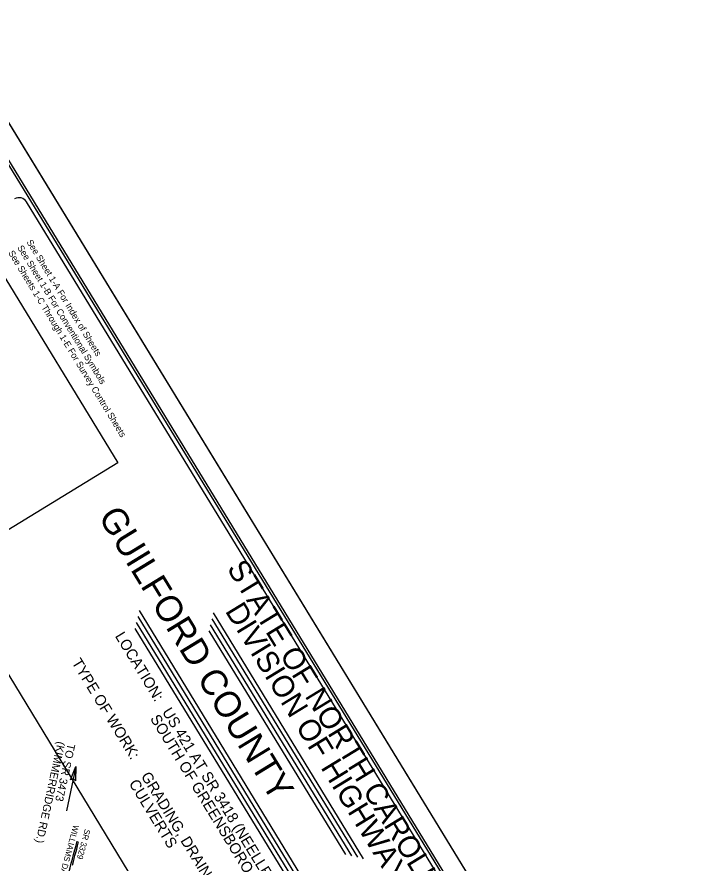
# Model space of a CAD drawing. Extents: x 1750583 to 1791140, y 783580 to 827376.
# Drawn here: x 1782418 to 1791140, y 815720 to 826460 of the extents above; entities that cross this region are included whole.
import ezdxf

# ---------------------------------------------------------------- set-up
doc = ezdxf.new("R2010")
doc.units = 0
for name, color, linetype in [('COGO Default Parcel', 7, 'Continuous'), ('Exist CMT EOP', 7, 'Continuous'), ('Prop Dimension Text', 7, 'Continuous'), ('Prop Terminator CELL', 7, 'Continuous'), ('Sheet Clip Boundary CELL', 7, 'Continuous'), ('Sheet Cutting Line CELL', 7, 'Continuous'), ('Sheet Data Field CELL', 7, 'Continuous'), ('Sheet Plot Border Inside CELL', 7, 'Continuous'), ('Sheet Plot Border Outside CELL', 7, 'Continuous'), ('Sheet Title CELL', 7, 'Continuous'), ('Sheet Title Data Points CELL', 7, 'Continuous')]:
    doc.layers.add(name, color=color, linetype=linetype)

msp = doc.modelspace()

# ---------------------------------------------------------------- linework, layer by layer
at = {"layer": 'COGO Default Parcel'}
msp.add_line((1783166, 816945), (1783048, 816382), dxfattribs=at)
at = {"layer": 'Exist CMT EOP'}
for points in [[(1782983, 815250), (1782998, 815306), (1783015, 815368), (1783030, 815426), (1783045, 815481), (1783062, 815545), (1783077, 815602), (1783093, 815661), (1783108, 815718), (1783116, 815746), (1783122, 815770), (1783138, 815829), (1783153, 815887), (1783168, 815943), (1783183, 815999)], [(1783123, 815695), (1783135, 815739), (1783144, 815774), (1783151, 815798), (1783155, 815816), (1783162, 815841), (1783169, 815866), (1783177, 815898), (1783188, 815939), (1783201, 815991)]]:
    msp.add_lwpolyline(points, dxfattribs=at)
at = {"layer": 'Prop Terminator CELL'}
msp.add_lwpolyline([(1783099, 816776), (1783166, 816945), (1783160, 816762), (1783133, 816791)], close=True, dxfattribs=at)
at = {"layer": 'Sheet Clip Boundary CELL'}
msp.add_lwpolyline([(1778137, 816039), (1779808, 813287), (1778788, 812657), (1781191, 808757), (1783068, 810931), (1785138, 813464), (1782098, 818459)], close=True, dxfattribs=at)
at = {"layer": 'Sheet Cutting Line CELL'}
msp.add_line((1781491, 826460), (1791140, 810668), dxfattribs=at)
at = {"layer": 'Sheet Plot Border Inside CELL'}
msp.add_lwpolyline([(1771461, 820164), (1781009, 804537), (1790904, 810582), (1781355, 826209)], close=True, dxfattribs=at)
at = {"layer": 'Sheet Plot Border Outside CELL'}
msp.add_lwpolyline([(1791140, 810668), (1781491, 826460), (1771176, 820157), (1780825, 804366)], close=True, dxfattribs=at)
at = {"layer": 'Sheet Title CELL'}
for p, q in [((1782148, 823340), (1783700, 820799)), ((1783700, 820799), (1780431, 818801)), ((1783969, 818924), (1786410, 814929)), ((1784908, 818896), (1786814, 815776)), ((1783951, 818848), (1786334, 814947)), ((1784890, 818821), (1786739, 815794)), ((1783914, 818697), (1786183, 814984)), ((1783933, 818773), (1786259, 814965)), ((1784871, 818745), (1786663, 815813)), ((1784853, 818670), (1786588, 815831))]:
    msp.add_line(p, q, dxfattribs=at)
for points in [[(1790751, 810778), (1782271, 824657)], [(1790675, 810797), (1782539, 824112)]]:
    msp.add_lwpolyline(points, dxfattribs=at)
msp.add_arc((1782446, 824055), 110, 31.4249, 121.4249, dxfattribs=at)
at = {"layer": 'Sheet Title Data Points CELL'}
msp.add_line((1785338, 816997), (1785338, 816997), dxfattribs=at)

# ---------------------------------------------------------------- texts
at = {"layer": 'Prop Dimension Text'}
for s, height, rotation, p in [('(KIMMERRIDGE RD.)', 100, 257.6975, (1782934, 817269)), ('TO SR 3473', 100, 257.6975, (1783062, 817241)), ('WILLIAMS DAIRY RD.', 75, 254.7784, (1783135, 816213)), ('SR 3329', 75, 254.7784, (1783280, 816157))]:
    msp.add_text(s, height=height, rotation=rotation, dxfattribs=at).set_placement(p)
at = {"layer": 'Sheet Data Field CELL'}
for s, height, p in [('       GUILFORD COUNTY       ', 330, (1782996, 820851)), ('SOUTH OF GREENSBORO                     ', 137.5, (1784104, 817554)), ('US 421 AT SR 3418 (NEELLEY ROAD)        ', 137.5, (1784256, 817640)), ('GRADING, DRAINAGE, PAVING, STRUCTURE AND ', 137.5, (1783988, 816825)), ('CULVERTS', 137.5, (1783834, 816731))]:
    msp.add_text(s, height=height, rotation=301.4249, dxfattribs=at).set_placement(p)
at = {"layer": 'Sheet Title CELL'}
for s, height, p in [('See Sheet 1-A For Index of Sheets', 82.42, (1782537, 823602)), ('See Sheet 1-B For Conventional Symbols', 82.5, (1782420, 823531)), ('See Sheets 1-C Through 1-E For Survey Control Sheets', 82.5, (1782304, 823465)), ('STATE OF NORTH CAROLINA', 274.73, (1785077, 819461)), ('DIVISION OF HIGHWAYS', 274.73, (1785054, 818920)), ('LOCATION: ', 137.4, (1783658, 818602)), ('TYPE OF WORK:', 137.37, (1783108, 818266))]:
    msp.add_text(s, height=height, rotation=301.4249, dxfattribs=at).set_placement(p)

doc.saveas('drawing.dxf')
